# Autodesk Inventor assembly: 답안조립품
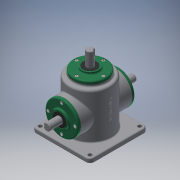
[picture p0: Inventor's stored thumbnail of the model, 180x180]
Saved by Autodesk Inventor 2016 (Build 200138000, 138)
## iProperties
Created: 2019-08
Part Number: 답안조립품
Material: 일반
Document SubType Name: Assembly
Designer: user
Author: user
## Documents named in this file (16)
- D:\490823V1013\답안조립품.iam
- D:\490823V1013\본체.ipt
- D:\490823V1013\메인 베벨기어.ipt
- D:\490823V1013\메인 축.ipt
- 메인 축.ipt
- D:\490823V1013\베어링 6203.ipt
- D:\490823V1013\볼트 M4.ipt
- 볼트 M4.ipt
- D:\490823V1013\서브 베벨기어.ipt
- D:\490823V1013\서브 축.ipt
- 서브 축.ipt
- D:\490823V1013\오일 실.ipt
- 오일 실.ipt
- D:\490823V1013\커버.ipt
- D:\490823V1013\키 4x4.ipt
- D:\490823V1013\키 5x5.ipt
